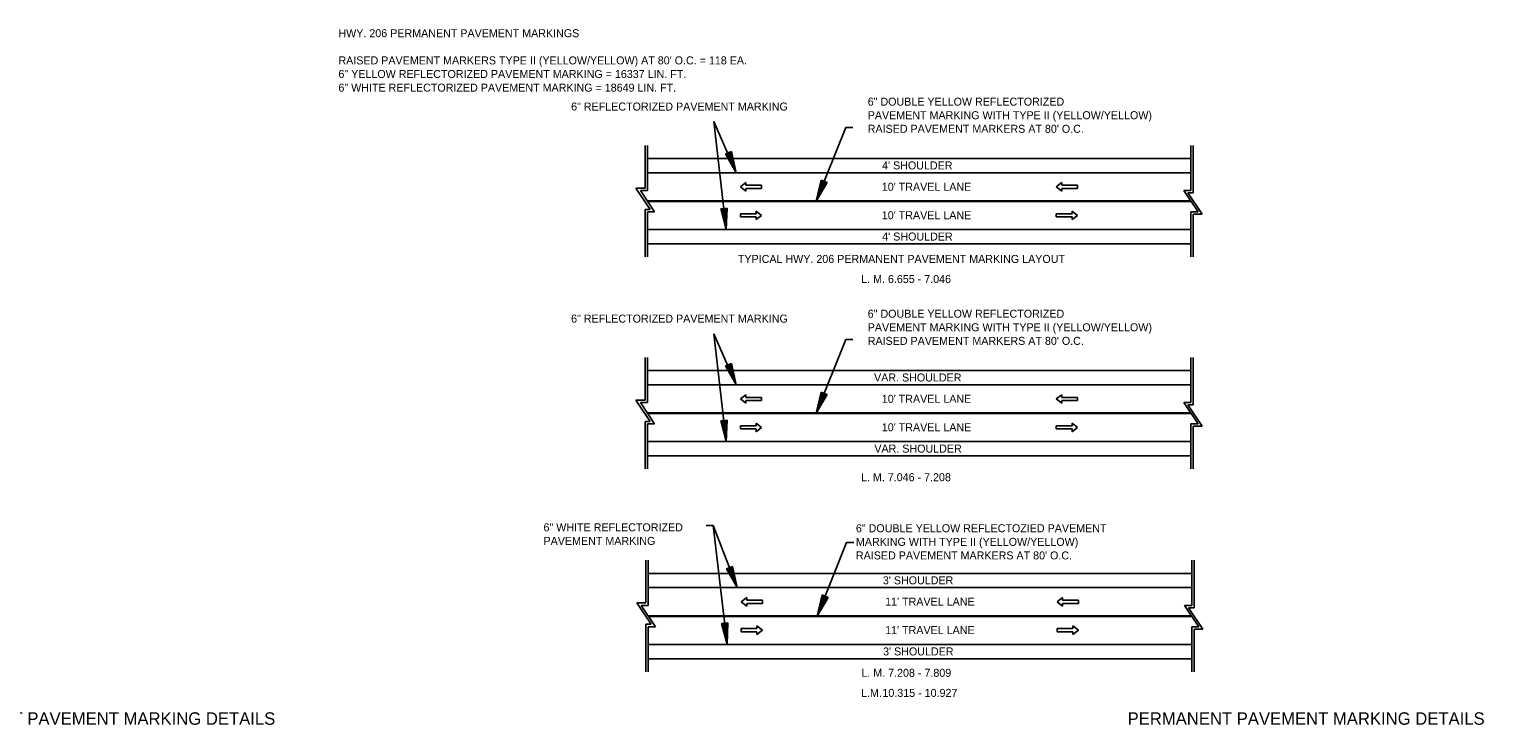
# Model space of a CAD drawing. Extents: x 2261938 to 2263136, y -3124572 to -3124216.
# Drawn here: x 2262931.8 to 2263136.3, y -3124313.5 to -3124215.6 of the extents above; entities that cross this region are included whole.
import ezdxf

# ---------------------------------------------------------------- set-up
doc = ezdxf.new("R2010")
doc.units = 0
for name, color, linetype in [('Default', 7, 'Continuous'), ('R_Draft', 7, 'Continuous'), ('SHET_Border-Text', 7, 'Continuous')]:
    doc.layers.add(name, color=color, linetype=linetype)

msp = doc.modelspace()

# ---------------------------------------------------------------- linework, layer by layer
at = {"layer": 'Default'}
for p, q in [((2263028.02, -3124228.66), (2263031.19, -3124235.84)), ((2263028.02, -3124228.66), (2263029.78, -3124243.84)), ((2263046.59, -3124229.48), (2263042.43, -3124239.84)), ((2263047.59, -3124229.48), (2263046.59, -3124229.48)), ((2263018.37, -3124232), (2263018.37, -3124238)), ((2263018.71, -3124232), (2263018.71, -3124238.34)), ((2263095.1, -3124232), (2263095.1, -3124238.34)), ((2263095.43, -3124232), (2263095.43, -3124238.67)), ((2263018.71, -3124233.84), (2263095.1, -3124233.84)), ((2263030.53, -3124232.88), (2263029.69, -3124233.2)), ((2263029.69, -3124233.2), (2263031.19, -3124235.84)), ((2263029.76, -3124233.17), (2263031.01, -3124235.37)), ((2263029.83, -3124233.14), (2263030.82, -3124234.89)), ((2263029.9, -3124233.12), (2263030.64, -3124234.42)), ((2263029.97, -3124233.09), (2263030.46, -3124233.95)), ((2263030.04, -3124233.06), (2263030.28, -3124233.48)), ((2263030.18, -3124233.01), (2263030.28, -3124233.48)), ((2263030.25, -3124232.98), (2263030.46, -3124233.95)), ((2263030.32, -3124232.96), (2263030.64, -3124234.42)), ((2263030.39, -3124232.93), (2263030.82, -3124234.89)), ((2263030.46, -3124232.9), (2263031.01, -3124235.37)), ((2263030.53, -3124232.88), (2263031.19, -3124235.84)), ((2263018.71, -3124235.84), (2263095.1, -3124235.84)), ((2263019.08, -3124241), (2263017.08, -3124238)), ((2263018.37, -3124238), (2263017.08, -3124238)), ((2263018.71, -3124238.34), (2263017.71, -3124238.34)), ((2263019.71, -3124241.34), (2263017.71, -3124238.34)), ((2263031.76, -3124237.84), (2263032.53, -3124237.24)), ((2263032.53, -3124238.44), (2263031.76, -3124237.84)), ((2263032.53, -3124237.61), (2263032.53, -3124237.24)), ((2263032.53, -3124237.61), (2263034.74, -3124237.61)), ((2263032.53, -3124238.06), (2263034.74, -3124238.06)), ((2263032.53, -3124238.44), (2263032.53, -3124238.06)), ((2263034.74, -3124238.06), (2263034.74, -3124237.61)), ((2263043.13, -3124236.89), (2263042.43, -3124239.84)), ((2263043.96, -3124237.22), (2263042.43, -3124239.84)), ((2263043.2, -3124236.91), (2263042.62, -3124239.37)), ((2263043.89, -3124237.19), (2263042.62, -3124239.37)), ((2263043.27, -3124236.94), (2263042.81, -3124238.89)), ((2263043.82, -3124237.16), (2263042.81, -3124238.89)), ((2263043.34, -3124236.97), (2263042.99, -3124238.43)), ((2263043.75, -3124237.14), (2263042.99, -3124238.43)), ((2263043.96, -3124237.22), (2263043.13, -3124236.89)), ((2263043.41, -3124237), (2263043.18, -3124237.96)), ((2263043.68, -3124237.11), (2263043.18, -3124237.96)), ((2263043.48, -3124237.03), (2263043.37, -3124237.49)), ((2263043.61, -3124237.08), (2263043.37, -3124237.49)), ((2263076.17, -3124237.84), (2263076.95, -3124237.24)), ((2263076.95, -3124238.44), (2263076.17, -3124237.84)), ((2263076.95, -3124237.61), (2263076.95, -3124237.24)), ((2263076.95, -3124237.61), (2263079.15, -3124237.61)), ((2263076.95, -3124238.06), (2263079.15, -3124238.06)), ((2263076.95, -3124238.44), (2263076.95, -3124238.06)), ((2263079.15, -3124238.06), (2263079.15, -3124237.61)), ((2263095.1, -3124238.34), (2263094.1, -3124238.34)), ((2263096.1, -3124241.34), (2263094.1, -3124238.34)), ((2263018.74, -3124239.89), (2263095.13, -3124239.89)), ((2263096.65, -3124241.67), (2263094.65, -3124238.67)), ((2263095.43, -3124238.67), (2263094.65, -3124238.67)), ((2263018.37, -3124241), (2263019.08, -3124241)), ((2263018.37, -3124247.67), (2263018.37, -3124241)), ((2263018.71, -3124247.67), (2263018.71, -3124241.34)), ((2263018.71, -3124241.34), (2263019.71, -3124241.34)), ((2263029.88, -3124240.81), (2263028.99, -3124240.91)), ((2263028.99, -3124240.91), (2263029.78, -3124243.84)), ((2263029.06, -3124240.9), (2263029.72, -3124243.34)), ((2263029.14, -3124240.89), (2263029.67, -3124242.83)), ((2263029.21, -3124240.88), (2263029.61, -3124242.33)), ((2263029.29, -3124240.87), (2263029.55, -3124241.83)), ((2263029.37, -3124240.87), (2263029.49, -3124241.33)), ((2263029.51, -3124240.85), (2263029.49, -3124241.33)), ((2263029.58, -3124240.84), (2263029.55, -3124241.83)), ((2263029.66, -3124240.83), (2263029.61, -3124242.33)), ((2263029.73, -3124240.82), (2263029.67, -3124242.83)), ((2263029.81, -3124240.81), (2263029.72, -3124243.34)), ((2263029.88, -3124240.81), (2263029.78, -3124243.84)), ((2263033.96, -3124241.61), (2263031.76, -3124241.61)), ((2263031.76, -3124241.61), (2263031.76, -3124242.06)), ((2263033.96, -3124242.06), (2263031.76, -3124242.06)), ((2263033.96, -3124241.24), (2263033.96, -3124241.61)), ((2263033.96, -3124241.24), (2263034.74, -3124241.84)), ((2263034.74, -3124241.84), (2263033.96, -3124242.44)), ((2263033.96, -3124242.06), (2263033.96, -3124242.44)), ((2263078.38, -3124241.61), (2263076.17, -3124241.61)), ((2263076.17, -3124241.61), (2263076.17, -3124242.06)), ((2263078.38, -3124242.06), (2263076.17, -3124242.06)), ((2263078.38, -3124241.24), (2263078.38, -3124241.61)), ((2263078.38, -3124241.24), (2263079.15, -3124241.84)), ((2263079.15, -3124241.84), (2263078.38, -3124242.44)), ((2263078.38, -3124242.06), (2263078.38, -3124242.44)), ((2263095.1, -3124247.67), (2263095.1, -3124241.34)), ((2263095.1, -3124241.34), (2263096.1, -3124241.34)), ((2263095.43, -3124247.67), (2263095.43, -3124241.67)), ((2263095.43, -3124241.67), (2263096.65, -3124241.67)), ((2263018.71, -3124243.84), (2263095.1, -3124243.84)), ((2263018.71, -3124245.84), (2263095.1, -3124245.84)), ((2263028.02, -3124258.48), (2263031.19, -3124265.66)), ((2263028.02, -3124258.48), (2263029.78, -3124273.66)), ((2263046.59, -3124259.3), (2263042.43, -3124269.66)), ((2263047.59, -3124259.3), (2263046.59, -3124259.3)), ((2263018.37, -3124261.82), (2263018.37, -3124267.82)), ((2263018.71, -3124261.82), (2263018.71, -3124268.16)), ((2263030.53, -3124262.69), (2263029.69, -3124263.02)), ((2263029.83, -3124262.96), (2263030.82, -3124264.71)), ((2263029.9, -3124262.94), (2263030.64, -3124264.24)), ((2263029.97, -3124262.91), (2263030.46, -3124263.77)), ((2263030.04, -3124262.88), (2263030.28, -3124263.3)), ((2263030.18, -3124262.83), (2263030.28, -3124263.3)), ((2263030.25, -3124262.8), (2263030.46, -3124263.77)), ((2263030.32, -3124262.77), (2263030.64, -3124264.24)), ((2263030.39, -3124262.75), (2263030.82, -3124264.71)), ((2263030.46, -3124262.72), (2263031.01, -3124265.19)), ((2263030.53, -3124262.69), (2263031.19, -3124265.66)), ((2263095.1, -3124261.82), (2263095.1, -3124268.16)), ((2263095.43, -3124261.82), (2263095.43, -3124268.49)), ((2263018.71, -3124263.66), (2263095.1, -3124263.66)), ((2263029.69, -3124263.02), (2263031.19, -3124265.66)), ((2263029.76, -3124262.99), (2263031.01, -3124265.19)), ((2263018.71, -3124265.66), (2263095.1, -3124265.66)), ((2263031.76, -3124267.66), (2263032.53, -3124267.06)), ((2263032.53, -3124267.43), (2263032.53, -3124267.06)), ((2263043.13, -3124266.7), (2263042.43, -3124269.66)), ((2263043.96, -3124267.04), (2263042.43, -3124269.66)), ((2263043.2, -3124266.73), (2263042.62, -3124269.19)), ((2263043.89, -3124267.01), (2263042.62, -3124269.19)), ((2263043.27, -3124266.76), (2263042.81, -3124268.71)), ((2263043.82, -3124266.98), (2263042.81, -3124268.71)), ((2263043.34, -3124266.79), (2263042.99, -3124268.25)), ((2263043.75, -3124266.96), (2263042.99, -3124268.25)), ((2263043.96, -3124267.04), (2263043.13, -3124266.7)), ((2263043.41, -3124266.82), (2263043.18, -3124267.78)), ((2263043.68, -3124266.93), (2263043.18, -3124267.78)), ((2263043.48, -3124266.85), (2263043.37, -3124267.31)), ((2263043.61, -3124266.9), (2263043.37, -3124267.31)), ((2263076.17, -3124267.66), (2263076.95, -3124267.06)), ((2263076.95, -3124267.43), (2263076.95, -3124267.06)), ((2263019.08, -3124270.82), (2263017.08, -3124267.82)), ((2263018.37, -3124267.82), (2263017.08, -3124267.82)), ((2263018.71, -3124268.16), (2263017.71, -3124268.16)), ((2263019.71, -3124271.16), (2263017.71, -3124268.16)), ((2263032.53, -3124268.26), (2263031.76, -3124267.66)), ((2263032.53, -3124267.43), (2263034.74, -3124267.43)), ((2263032.53, -3124267.88), (2263034.74, -3124267.88)), ((2263032.53, -3124268.26), (2263032.53, -3124267.88)), ((2263034.74, -3124267.88), (2263034.74, -3124267.43)), ((2263076.95, -3124268.26), (2263076.17, -3124267.66)), ((2263076.95, -3124267.43), (2263079.15, -3124267.43)), ((2263076.95, -3124267.88), (2263079.15, -3124267.88)), ((2263076.95, -3124268.26), (2263076.95, -3124267.88)), ((2263079.15, -3124267.88), (2263079.15, -3124267.43)), ((2263095.1, -3124268.16), (2263094.1, -3124268.16)), ((2263096.1, -3124271.16), (2263094.1, -3124268.16)), ((2263096.65, -3124271.49), (2263094.65, -3124268.49)), ((2263095.43, -3124268.49), (2263094.65, -3124268.49)), ((2263018.37, -3124270.82), (2263019.08, -3124270.82)), ((2263018.37, -3124277.49), (2263018.37, -3124270.82)), ((2263018.71, -3124277.49), (2263018.71, -3124271.16)), ((2263018.71, -3124271.16), (2263019.71, -3124271.16)), ((2263018.74, -3124269.71), (2263095.13, -3124269.71)), ((2263029.88, -3124270.62), (2263028.99, -3124270.73)), ((2263028.99, -3124270.73), (2263029.78, -3124273.66)), ((2263029.06, -3124270.72), (2263029.72, -3124273.16)), ((2263029.14, -3124270.71), (2263029.67, -3124272.65)), ((2263029.21, -3124270.7), (2263029.61, -3124272.15)), ((2263029.29, -3124270.69), (2263029.55, -3124271.64)), ((2263029.37, -3124270.68), (2263029.49, -3124271.15)), ((2263029.51, -3124270.67), (2263029.49, -3124271.15)), ((2263029.58, -3124270.66), (2263029.55, -3124271.64)), ((2263029.66, -3124270.65), (2263029.61, -3124272.15)), ((2263029.73, -3124270.64), (2263029.67, -3124272.65)), ((2263029.81, -3124270.63), (2263029.72, -3124273.16)), ((2263029.88, -3124270.62), (2263029.78, -3124273.66)), ((2263033.96, -3124271.06), (2263033.96, -3124271.43)), ((2263033.96, -3124271.06), (2263034.74, -3124271.66)), ((2263078.38, -3124271.06), (2263078.38, -3124271.43)), ((2263078.38, -3124271.06), (2263079.15, -3124271.66)), ((2263095.1, -3124277.49), (2263095.1, -3124271.16)), ((2263095.1, -3124271.16), (2263096.1, -3124271.16)), ((2263033.96, -3124271.43), (2263031.76, -3124271.43)), ((2263031.76, -3124271.43), (2263031.76, -3124271.88)), ((2263033.96, -3124271.88), (2263031.76, -3124271.88)), ((2263034.74, -3124271.66), (2263033.96, -3124272.26)), ((2263033.96, -3124271.88), (2263033.96, -3124272.26)), ((2263078.38, -3124271.43), (2263076.17, -3124271.43)), ((2263076.17, -3124271.43), (2263076.17, -3124271.88)), ((2263078.38, -3124271.88), (2263076.17, -3124271.88)), ((2263079.15, -3124271.66), (2263078.38, -3124272.26)), ((2263078.38, -3124271.88), (2263078.38, -3124272.26)), ((2263095.43, -3124277.49), (2263095.43, -3124271.49)), ((2263095.43, -3124271.49), (2263096.65, -3124271.49)), ((2263018.71, -3124273.66), (2263095.1, -3124273.66)), ((2263018.71, -3124275.66), (2263095.1, -3124275.66)), ((2263026.95, -3124285.46), (2263027.95, -3124285.46)), ((2263027.95, -3124285.46), (2263031.3, -3124294.18)), ((2263027.95, -3124285.46), (2263029.9, -3124302.18)), ((2263046.7, -3124287.82), (2263042.54, -3124298.18)), ((2263047.7, -3124287.82), (2263046.7, -3124287.82)), ((2263018.48, -3124290.34), (2263018.48, -3124296.34)), ((2263018.82, -3124290.34), (2263018.82, -3124296.68)), ((2263030.64, -3124291.21), (2263029.8, -3124291.54)), ((2263029.8, -3124291.54), (2263031.3, -3124294.18)), ((2263029.87, -3124291.51), (2263031.12, -3124293.71)), ((2263029.94, -3124291.48), (2263030.93, -3124293.23)), ((2263030.01, -3124291.46), (2263030.75, -3124292.76)), ((2263030.09, -3124291.43), (2263030.57, -3124292.29)), ((2263030.16, -3124291.4), (2263030.39, -3124291.82)), ((2263030.29, -3124291.35), (2263030.39, -3124291.82)), ((2263030.36, -3124291.32), (2263030.57, -3124292.29)), ((2263030.43, -3124291.3), (2263030.75, -3124292.76)), ((2263030.5, -3124291.27), (2263030.93, -3124293.23)), ((2263030.57, -3124291.24), (2263031.12, -3124293.71)), ((2263030.64, -3124291.21), (2263031.3, -3124294.18)), ((2263095.21, -3124290.34), (2263095.21, -3124296.68)), ((2263095.54, -3124290.34), (2263095.54, -3124297.01)), ((2263018.82, -3124292.18), (2263095.21, -3124292.18)), ((2263018.82, -3124294.18), (2263095.21, -3124294.18)), ((2263031.87, -3124296.18), (2263032.65, -3124295.58)), ((2263032.65, -3124295.95), (2263032.65, -3124295.58)), ((2263043.24, -3124295.22), (2263042.54, -3124298.18)), ((2263044.08, -3124295.56), (2263042.54, -3124298.18)), ((2263043.31, -3124295.25), (2263042.73, -3124297.71)), ((2263044.01, -3124295.53), (2263042.73, -3124297.71)), ((2263043.38, -3124295.28), (2263042.92, -3124297.23)), ((2263043.94, -3124295.5), (2263042.92, -3124297.23)), ((2263043.45, -3124295.31), (2263043.11, -3124296.77)), ((2263043.87, -3124295.48), (2263043.11, -3124296.77)), ((2263044.08, -3124295.56), (2263043.24, -3124295.22)), ((2263043.52, -3124295.34), (2263043.3, -3124296.3)), ((2263043.79, -3124295.45), (2263043.3, -3124296.3)), ((2263043.59, -3124295.37), (2263043.48, -3124295.83)), ((2263043.72, -3124295.42), (2263043.48, -3124295.83)), ((2263076.28, -3124296.18), (2263077.06, -3124295.58)), ((2263077.06, -3124295.95), (2263077.06, -3124295.58)), ((2263019.2, -3124299.34), (2263017.2, -3124296.34)), ((2263018.48, -3124296.34), (2263017.2, -3124296.34)), ((2263018.82, -3124296.68), (2263017.82, -3124296.68)), ((2263019.82, -3124299.68), (2263017.82, -3124296.68)), ((2263032.65, -3124296.78), (2263031.87, -3124296.18)), ((2263032.65, -3124295.95), (2263034.85, -3124295.95)), ((2263032.65, -3124296.4), (2263034.85, -3124296.4)), ((2263032.65, -3124296.78), (2263032.65, -3124296.4)), ((2263034.85, -3124296.4), (2263034.85, -3124295.95)), ((2263077.06, -3124296.78), (2263076.28, -3124296.18)), ((2263077.06, -3124295.95), (2263079.27, -3124295.95)), ((2263077.06, -3124296.4), (2263079.27, -3124296.4)), ((2263077.06, -3124296.78), (2263077.06, -3124296.4)), ((2263079.27, -3124296.4), (2263079.27, -3124295.95)), ((2263095.21, -3124296.68), (2263094.21, -3124296.68)), ((2263096.21, -3124299.68), (2263094.21, -3124296.68)), ((2263096.76, -3124300.01), (2263094.76, -3124297.01)), ((2263095.54, -3124297.01), (2263094.76, -3124297.01)), ((2263018.48, -3124299.34), (2263019.2, -3124299.34)), ((2263018.48, -3124306.01), (2263018.48, -3124299.34)), ((2263018.78, -3124298.13), (2263095.18, -3124298.13)), ((2263018.82, -3124306.01), (2263018.82, -3124299.68)), ((2263018.82, -3124299.68), (2263019.82, -3124299.68)), ((2263018.85, -3124298.23), (2263095.24, -3124298.23)), ((2263030, -3124299.14), (2263029.1, -3124299.25)), ((2263029.1, -3124299.25), (2263029.9, -3124302.18)), ((2263029.18, -3124299.24), (2263029.84, -3124301.68)), ((2263029.25, -3124299.23), (2263029.78, -3124301.17)), ((2263029.33, -3124299.22), (2263029.72, -3124300.67)), ((2263029.4, -3124299.21), (2263029.66, -3124300.16)), ((2263029.48, -3124299.2), (2263029.6, -3124299.67)), ((2263029.62, -3124299.19), (2263029.6, -3124299.67)), ((2263029.69, -3124299.18), (2263029.66, -3124300.16)), ((2263029.77, -3124299.17), (2263029.72, -3124300.67)), ((2263029.85, -3124299.16), (2263029.78, -3124301.17)), ((2263029.92, -3124299.15), (2263029.84, -3124301.68)), ((2263030, -3124299.14), (2263029.9, -3124302.18)), ((2263034.08, -3124299.58), (2263034.08, -3124299.95)), ((2263034.08, -3124299.58), (2263034.85, -3124300.18)), ((2263078.49, -3124299.58), (2263078.49, -3124299.95)), ((2263078.49, -3124299.58), (2263079.27, -3124300.18)), ((2263095.21, -3124306.01), (2263095.21, -3124299.68)), ((2263095.21, -3124299.68), (2263096.21, -3124299.68)), ((2263034.08, -3124299.95), (2263031.87, -3124299.95)), ((2263031.87, -3124299.95), (2263031.87, -3124300.4)), ((2263034.08, -3124300.4), (2263031.87, -3124300.4)), ((2263034.85, -3124300.18), (2263034.08, -3124300.78)), ((2263034.08, -3124300.4), (2263034.08, -3124300.78)), ((2263078.49, -3124299.95), (2263076.28, -3124299.95)), ((2263076.28, -3124299.95), (2263076.28, -3124300.4)), ((2263078.49, -3124300.4), (2263076.28, -3124300.4)), ((2263079.27, -3124300.18), (2263078.49, -3124300.78)), ((2263078.49, -3124300.4), (2263078.49, -3124300.78)), ((2263095.54, -3124306.01), (2263095.54, -3124300.01)), ((2263095.54, -3124300.01), (2263096.76, -3124300.01)), ((2263018.82, -3124302.18), (2263095.21, -3124302.18)), ((2263018.82, -3124304.18), (2263095.21, -3124304.18))]:
    msp.add_line(p, q, dxfattribs=at)
at = {"layer": 'R_Draft'}
for p, q in [((2263018.67, -3124239.79), (2263095.06, -3124239.79)), ((2263018.67, -3124269.61), (2263095.06, -3124269.61))]:
    msp.add_line(p, q, dxfattribs=at)

# ---------------------------------------------------------------- texts
at = {"layer": 'Default'}
for s, p in [('HWY. 206 PERMANENT PAVEMENT MARKINGS', (2262975.26, -3124216.79)), ("RAISED PAVEMENT MARKERS TYPE II (YELLOW/YELLOW) AT 80' O.C. = 118 EA.", (2262975.26, -3124220.61)), ('6" YELLOW REFLECTORIZED PAVEMENT MARKING = 16337 LIN. FT.', (2262975.26, -3124222.52)), ('6" WHITE REFLECTORIZED PAVEMENT MARKING = 18649 LIN. FT.', (2262975.26, -3124224.44)), ('6" REFLECTORIZED PAVEMENT MARKING', (2263007.97, -3124227.1)), ('6" DOUBLE YELLOW REFLECTORIZED', (2263049.66, -3124226.41)), ('PAVEMENT MARKING WITH TYPE II (YELLOW/YELLOW)', (2263049.66, -3124228.32)), ("RAISED PAVEMENT MARKERS AT 80' O.C.", (2263049.66, -3124230.23)), ("4' SHOULDER", (2263051.68, -3124235.38)), ("10' TRAVEL LANE", (2263051.64, -3124238.38)), ("10' TRAVEL LANE", (2263051.64, -3124242.38)), ("4' SHOULDER", (2263051.7, -3124245.38)), ('TYPICAL HWY. 206 PERMANENT PAVEMENT MARKING LAYOUT', (2263031.41, -3124248.53)), ('L. M. 6.655 - 7.046', (2263048.74, -3124251.35)), ('6" REFLECTORIZED PAVEMENT MARKING', (2263007.97, -3124256.92)), ('6" DOUBLE YELLOW REFLECTORIZED', (2263049.66, -3124256.23)), ('PAVEMENT MARKING WITH TYPE II (YELLOW/YELLOW)', (2263049.66, -3124258.14)), ("RAISED PAVEMENT MARKERS AT 80' O.C.", (2263049.66, -3124260.05)), ('VAR. SHOULDER', (2263050.55, -3124265.2)), ("10' TRAVEL LANE", (2263051.64, -3124268.2)), ("10' TRAVEL LANE", (2263051.64, -3124272.2)), ('VAR. SHOULDER', (2263050.59, -3124275.2)), ('L. M. 7.046 - 7.208', (2263048.72, -3124279.22)), ('6" WHITE REFLECTORIZED', (2263004.09, -3124286.27)), ('6" DOUBLE YELLOW REFLECTOZIED PAVEMENT', (2263048, -3124286.4)), ('PAVEMENT MARKING', (2263004.09, -3124288.18)), ('MARKING WITH TYPE II (YELLOW/YELLOW)', (2263048, -3124288.31)), ("RAISED PAVEMENT MARKERS AT 80' O.C.", (2263048, -3124290.22)), ("3' SHOULDER", (2263051.79, -3124293.72)), ("11' TRAVEL LANE", (2263052.11, -3124296.72)), ("11' TRAVEL LANE", (2263052.11, -3124300.72)), ("3' SHOULDER", (2263051.82, -3124303.72)), ('L. M. 7.208 - 7.809', (2263048.77, -3124306.73)), ('L.M.', (2263048.72, -3124309.55)), ('  10.315 - 10.927', (2263050.89, -3124309.55))]:
    msp.add_text(s, height=1.125, dxfattribs=at).set_placement(p)
at = {"layer": 'SHET_Border-Text'}
for p in [(2262916.19, -3124313.47), (2263086.19, -3124313.47)]:
    msp.add_text('PERMANENT PAVEMENT MARKING DETAILS', height=1.75, dxfattribs=at).set_placement(p)

doc.saveas('drawing.dxf')
